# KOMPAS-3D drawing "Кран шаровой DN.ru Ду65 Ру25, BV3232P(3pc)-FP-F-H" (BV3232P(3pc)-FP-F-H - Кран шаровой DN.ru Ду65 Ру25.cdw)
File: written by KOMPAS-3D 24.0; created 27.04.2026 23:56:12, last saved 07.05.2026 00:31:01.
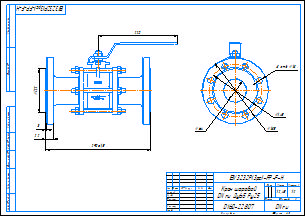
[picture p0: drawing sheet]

Document properties: Автор: Максим; Форматы листов документа: A3; Полное имя файла: BVxxP(3pc)-FP-F-H - Кран шаровой DN.ru Ду65 Ру25.cdw; Масса: 12.445; Наименование: Кран шаровой DN.ru Ду65 Ру25; Количество листов документа: 1; Примечание: D160-22807

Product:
- Body: Тело 1  | qty 1
    Масса: 13.766972
- Part/product: Кран шаровой DN.ru Ду65 Ру25  | designation BV3232P(3pc)-FP-F-H
    Масса: 12.445
    Раздел спецификации: Прочие изделия
    Форматы листов документа: A3
    Примечание: D160-22807

Views: Вид 1, Вид:2, Проекционный вид 2, Вид:1
Referenced files in D:\Rabota ebanaya\Апрель\BVxxP(3pc)-FP-F-H Кран шаровой Ду15-100\Исходники\DN65\: BVxxP(3pc)-FP-F-H - Кран шаровой DN.ru Ду65 Ру25.m3d, BVxxP(3pc)-FP-F-H - Кран шаровой DN.ru Ду65 Ру25.cdw
Referenced files in D:\Rabota ebanaya\Апрель\BV3232P(3pc)-FP-F-H Кран шаровой Ду15-100\Исходники\DN65\: BV3232P(3pc)-FP-F-H - Кран шаровой DN.ru Ду65 Ру25.m3d
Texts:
  Линейный размер
  BV3232P(3pc)-FP-F-H
  Диаметральный размер
  Кран шаровой
  DN.ru Ду65 Ру25
  Кран шаровой DN.ru Ду65 Ру25
  BV3232P(3pc)-FP-F-H Кран шаровой DN.ru Ду65 Ру25
Dimensions and other numbers on the sheet: 0; 3; 2; 4; 220; 122; 290±1,5; 22; 145; 185; 64; 8 отв.; 18; 1:2; 1; 12,45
